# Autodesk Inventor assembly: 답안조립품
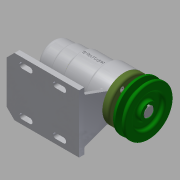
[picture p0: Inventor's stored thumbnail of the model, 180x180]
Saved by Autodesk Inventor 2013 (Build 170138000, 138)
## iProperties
Created: 2017-09
Part Number: 답안조립품
Document SubType Name: Assembly
Designer: Windows7
Author: Windows7
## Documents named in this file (12)
- C:\Users\Windows7\Desktop\470908V1012\답안조립품.iam
- C:\Users\Windows7\Desktop\470908V1012\축.ipt
- C:\Users\Windows7\Desktop\470908V1012\베어링 6004.ipt
- C:\Users\Windows7\Desktop\470908V1012\어댑터슬리브.ipt
- C:\Users\Windows7\Desktop\470908V1012\볼트 M4 x 12.ipt
- C:\Users\Windows7\Desktop\470908V1012\베어링 51202.ipt
- C:\Users\Windows7\Desktop\470908V1012\본체.ipt
- C:\Users\Windows7\Desktop\470908V1012\커버.ipt
- C:\Users\Windows7\Desktop\470908V1012\오일 실 20x35x7.ipt
- C:\Users\Windows7\Desktop\470908V1012\V벨트풀리.ipt
- C:\Users\Windows7\Desktop\470908V1012\키 5 x 5 x 16.ipt
- C:\Users\Windows7\Desktop\470908V1012\멈춤나사 M3x8.ipt
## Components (1 placed, 1 different names)
1. V벨트풀리:1 — 각도:1, 각도:2
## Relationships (2: Angle 2)
- 각도:1 [Angle]: V벨트풀리:1
- 각도:2 [Angle]: V벨트풀리:1
